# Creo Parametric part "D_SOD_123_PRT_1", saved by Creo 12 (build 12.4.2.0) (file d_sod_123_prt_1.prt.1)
Units: Custom; MM, KILOGRAM, SECS

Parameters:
  PTC_WM_ITERATION = "0"
  PTC_WM_VERSION = "-.0"
  PTC_WM_LIFECYCLE_STATE = "In Work"
  PTC_WM_LIFECYCLE = "MO_CADDocument"
  PTC_WM_CREATED_BY = "Maximilian Roepper (Z0017RMS: MO)"
  PTC_WM_CREATED_ON = "18-Sep-26 11:36:42 AM"
  PTC_WM_MODIFIED_BY = "Maximilian Roepper (Z0017RMS: MO)"
  PTC_WM_MODIFIED_ON = "18-Sep-26 11:36:46 AM"
  PDMLINKNUMBER = "PDM000071455022"
  PTC_WM_NAME = "d_sod_123_prt_1.prt"
  PTC_WM_NUMBER = "PDM000071455022"

Other parameters: WEIGHT, WEIGHT_FACTOR, WEIGHT_ADD, _MASS_TEMP, _DIFF_TEMP, MC_ERRORS, SUPPLIER

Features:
  1. coordinate system
  2. datum plane "PRT_YZ"
  3. datum plane "PRT_XY"
  4. datum plane "PRT_XZ"
  5. coordinate system
  6. datum axis
  7. datum axis
  8. datum axis
  9. coordinate system
  10. imported feature
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
Other named items: PRT, SIEMENS_MO, DRW_VIEW_ORG, PRT_X, PRT_Y, PRT_Z, CS0, ROUGH_GROB

Layers: 00_STD_CSYS-KSYS, 01_STD_PLANES-EBENEN, 02_STD_AXES-ACHSEN, 03_STD_CSYS-KSYS, 24_IMPORT_FEAT-IMPORT_KE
